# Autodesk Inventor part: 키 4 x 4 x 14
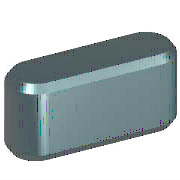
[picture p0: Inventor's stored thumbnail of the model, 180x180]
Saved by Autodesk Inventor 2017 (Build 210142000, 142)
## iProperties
Created: 2012-02
Part Number: 키 4 x 4 x 14
Material: 강철, 연강
Description: 키 및 해당 키홈
Document SubType Name: Modeling
Standard: KS B 1311
Designer: test
Standards Organization: KS
Language: ko-KR
Size Designation: 4 x 4 x 14
Categories: <MemberInstance><Categories><Category DisplayName="샤프트 부품" InternalName="7f7aeb1f-a693-4053-b835-cee3144e0d98" Mnemonic="SHFT"><Category DisplayName="키" Interna
Density: 1 g/cm^3
Appearance: 노란색
IsCustomPart: 1
Author: test
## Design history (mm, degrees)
workplane "Work Plane1"
workplane "Work Plane2"
sketch "스케치1"
  geometry: L1 (2, 2)-(12, 2); L2 (12, -2)-(2, -2); L3 (0, 9.4)-(0, -7.4) reference; L4 (-5, 0)-(30, 0) reference; L5 (14, 0)-(14, 7); A1 r 2 centre (2, 0) between (2, 2) and (2, -2); A2 r 2 centre (12, 0) between (12, -2) and (12, 2)
  constraints: 6 end point, 5 point on circle, 4 tangent, 3 point on line, 2 centre point, 1 horizontal, 1 parallel, 1 perpendicular
  dimensions: "d0" = 2 radius of A1 (= 0.5 x PB); "d13" = 2 radius of A2 (= 0.5 x PB); "d14" = 14 distance between parallel lines of L5 L3 (= NLG)
extrude "본체1" new body sketch "스케치1" taper "d3" = 0 deg; stored distance "d4" = 10
workplane "Work Plane3"
body "Solid1"
chamfer "모따기1" distance "d8" = 0.25 (= PHH); stored, may be unused: second distance "d9" = 0.25 (= PHH), angle "d15" = 45 deg
other parameters: "d1" = -2.5 (= -PNT), "d2" = 1.5 (= PH - PNT), "NLG" = 14 [user parameter; used in 3 equation terms], "PB" = 4 [user parameter; used in 2 equation terms], "PNT" = 2.5 [user parameter; used in 2 equation terms], "PH" = 4 [user parameter; used in 1 equation term], "PHH" = 0.25 [user parameter; used in 2 equation terms], "d10" = 0, "d16" = 0, "d17" = 0, "d18" = 0, "PLB2" = 14 (= NLG) [user parameter], "WDMAX" = 12 [user parameter], "PLB1" = 14 (= NLG) [user parameter], "RR" = 0.08 [user parameter], "PUEB" = 1.8 [user parameter]
